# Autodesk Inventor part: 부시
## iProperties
Company: 한국ATC센터
Created: 2014-11
Part Number: 부시
Document SubType Name: Modeling
Designer: KYOUNG IL JANG
Density: 7.86 g/cm^3
Material: 강, 연강
Mass: 167.601 g
Surface Area: 70.0223 cm^2
Volume: 21.3233 cm^3
Author: KYOUNG IL JANG
